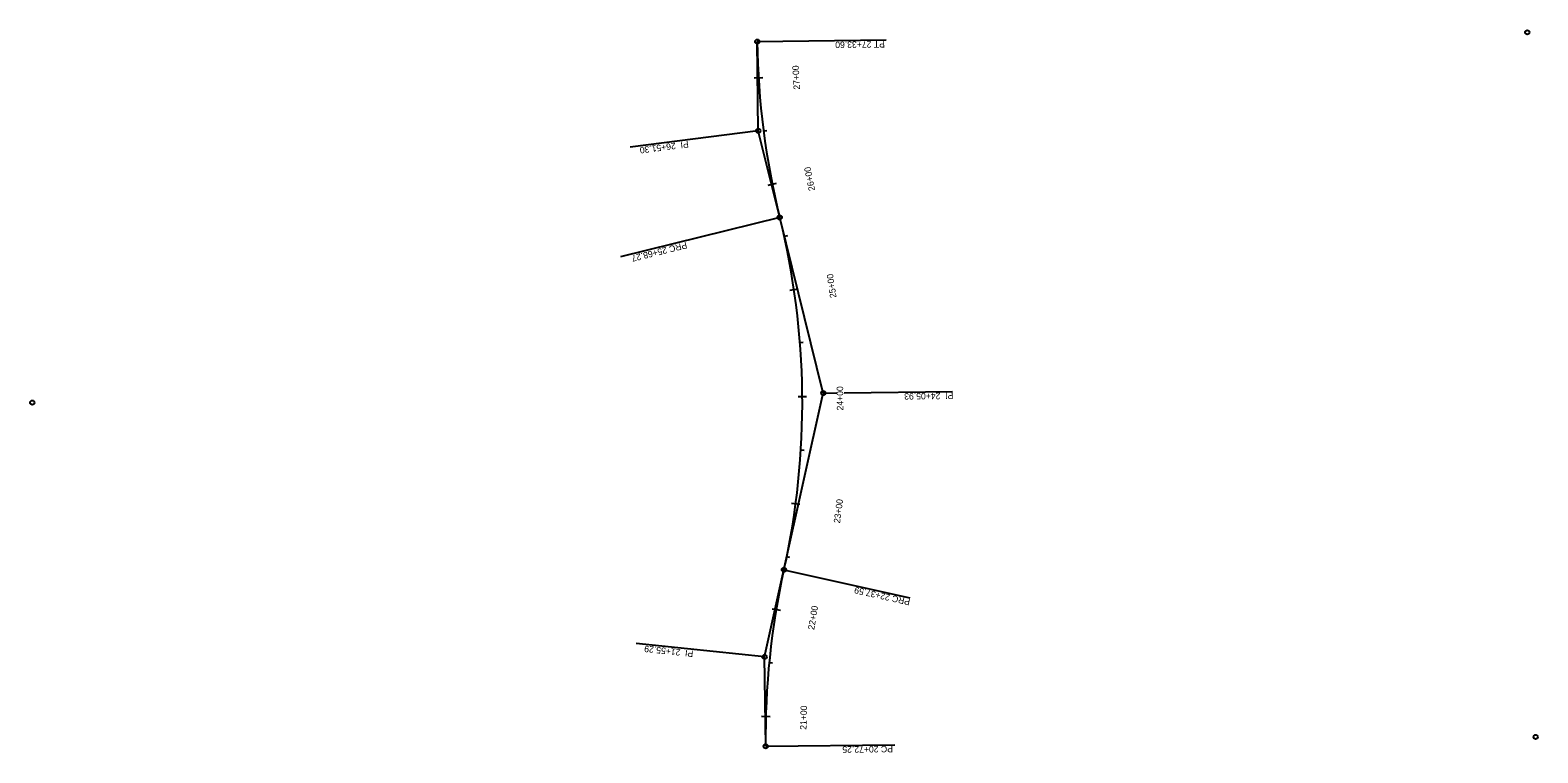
# Model space of a CAD drawing. Extents: x 1804270 to 1805673, y 517407 to 518079.
import ezdxf

# ---------------------------------------------------------------- set-up
doc = ezdxf.new("R2010")
doc.units = 0
for name, color, linetype in [('Default', 7, 'Continuous'), ('Level 56', 7, 'Continuous'), ('Level 59', 7, 'Continuous')]:
    doc.layers.add(name, color=color, linetype=linetype)

msp = doc.modelspace()

# ---------------------------------------------------------------- linework, layer by layer
at = {"layer": 'Default'}
for centre, start, end in [((1805662.8, 518077.4), 180.688, 193.9151), ((1804272.4, 517733), 347.461, 13.9151), ((1805670.6, 517422), 167.461, 180.6881)]:
    msp.add_arc(centre, 716.2, start, end, dxfattribs=at)
at = {"layer": 'Level 56'}
for p, q in [((1804947.6, 517985.8), (1804946.6, 518068.8)), ((1804947.6, 517985.8), (1804946.6, 518068.8)), ((1804967.6, 517905.2), (1804947.6, 517985.8)), ((1804967.6, 517905.2), (1804947.6, 517985.8)), ((1805008.1, 517741.8), (1804967.6, 517905.2)), ((1805008.1, 517741.8), (1804967.6, 517905.2)), ((1804971.5, 517577.5), (1805008.1, 517741.8)), ((1804971.5, 517577.5), (1805008.1, 517741.8)), ((1804953.5, 517496.4), (1804971.5, 517577.5)), ((1804953.5, 517496.4), (1804971.5, 517577.5)), ((1804954.5, 517413.4), (1804953.5, 517496.4)), ((1804954.5, 517413.4), (1804953.5, 517496.4))]:
    msp.add_line(p, q, dxfattribs=at)
for points in [[(1804946.6, 518068.8), (1805066.6, 518070.3)], [(1804943.8, 518035), (1804951.8, 518035.5)], [(1804947.6, 517985.8), (1804828.6, 517970.6)], [(1804955.5, 517985.9), (1804952.5, 517985.5)], [(1804956.7, 517935.4), (1804964.6, 517937)], [(1804967.6, 517905.2), (1804819.5, 517868.5)], [(1804974.7, 517888.1), (1804971.8, 517887.4)], [(1804976.9, 517837.7), (1804984.8, 517838.8)], [(1804989.4, 517788.8), (1804986.4, 517788.6)], [(1804984.6, 517738.6), (1804992.6, 517738.7)], [(1805008.1, 517741.8), (1805020.8, 517742)], [(1805027.5, 517742), (1805128.1, 517743.2)], [(1804990.2, 517688.5), (1804987.2, 517688.7)], [(1804978.4, 517639.4), (1804986.4, 517638.4)], [(1804971.5, 517577.5), (1805088.7, 517551.4)], [(1804977.1, 517589), (1804974.1, 517589.6)], [(1804960.4, 517541.3), (1804968.3, 517539.9)], [(1804953.5, 517496.4), (1804834.1, 517508.8)], [(1804960.8, 517490.7), (1804957.8, 517491)], [(1804950.7, 517441.2), (1804958.7, 517441)], [(1804954.5, 517413.4), (1805074.5, 517414.8)]]:
    msp.add_lwpolyline(points, dxfattribs=at)
for centre in [(1804946.6, 518068.8), (1804946.6, 518068.8), (1804946.6, 518068.8), (1805662.8, 518077.4), (1805662.8, 518077.4), (1804947.6, 517985.8), (1804947.6, 517985.8), (1804967.6, 517905.2), (1804967.6, 517905.2), (1804967.6, 517905.2), (1804272.4, 517733), (1804272.4, 517733), (1805008.1, 517741.8), (1805008.1, 517741.8), (1804971.5, 517577.5), (1804971.5, 517577.5), (1804971.5, 517577.5), (1804953.5, 517496.4), (1804953.5, 517496.4), (1805670.6, 517422), (1805670.6, 517422), (1804954.5, 517413.4), (1804954.5, 517413.4), (1804954.5, 517413.4)]:
    msp.add_circle(centre, 2, dxfattribs=at)
at = {"layer": 'Level 59'}
for centre, start, end in [((1805662.8, 518077.4), 180.688, 193.9151), ((1805662.8, 518077.4), 180.688, 193.9151), ((1804272.4, 517733), 347.461, 13.9151), ((1804272.4, 517733), 347.461, 13.9151), ((1805670.6, 517422), 167.461, 180.6881), ((1805670.6, 517422), 167.461, 180.6881)]:
    msp.add_arc(centre, 716.2, start, end, dxfattribs=at)

# ---------------------------------------------------------------- texts
at = {"layer": 'Level 56'}
for s, rotation, p in [('PT 27+33.60', 180.688, (1805065.3, 518069.3)), ('27+00', 93.3763, (1804986.5, 518024.3)), ('PI  26+51.30', 187.3016, (1804882.4, 517976.4)), ('26+00', 101.3763, (1805000.5, 517930.6)), ('PRC 25+68.27', 193.9151, (1804880.5, 517882.5)), ('25+00', 98.4539, (1805020.4, 517830.8)), ('24+00', 90.4539, (1805026.7, 517725.7)), ('PI  24+05.93', 180.688, (1805129, 517742.3)), ('23+00', 82.4539, (1805023.6, 517620.5)), ('PRC 22+37.59', 167.461, (1805089.3, 517550.2)), ('22+00', 80.4681, (1804999.6, 517521.3)), ('PI  21+55.29', 174.0745, (1804887.4, 517502.3)), ('21+00', 88.4681, (1804992.4, 517428.6)), ('PC 20+72.25', 180.6881, (1805072.8, 517413.8))]:
    msp.add_text(s, height=6, rotation=rotation, dxfattribs=at).set_placement(p)

doc.saveas('drawing.dxf')
